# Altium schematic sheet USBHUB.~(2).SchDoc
size A
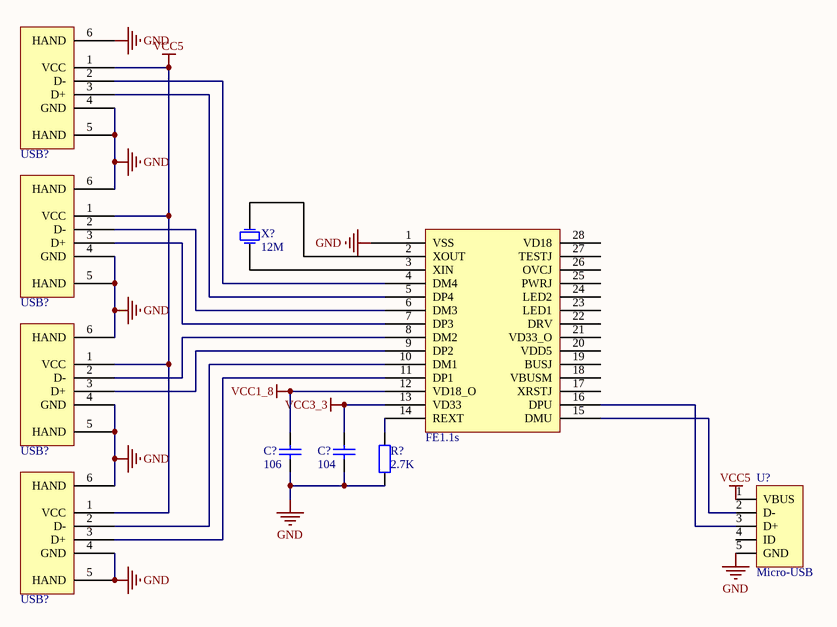
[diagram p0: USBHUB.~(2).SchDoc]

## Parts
(Parts that share a designator on the sheet are numbered #1, #2 ... from top to bottom, then left to right.)
C?#1  value 106  [2012[0805]-C]  (hidden comment: Cap1)
C?#2  value 104  [2012[0805]-C]  (hidden comment: Cap1)
FE1.1s  FE1.1s  [SSOP-28]  (value not drawn)
R?  value 2.7K  [2012[0805]-R]  (hidden comment: Res1)
U?  Micro-USB  [Micro-USB]
USB?#1  USB  [USB2.5-2V4A]  (value not drawn)
USB?#2  USB  [USB2.5-2V4A]  (value not drawn)
USB?#3  USB  [USB2.5-2V4A]  (value not drawn)
USB?#4  USB  [USB2.5-2V4A]  (value not drawn)
X?  12M  [XTAL]

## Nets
GND: C?#1.1 C?#2.1 R?.1 U?.5(GND) USB?#1.4(GND) USB?#1.5(HAND) USB?#1.6(HAND) USB?#2.4(GND) USB?#2.5(HAND) USB?#2.6(HAND) USB?#3.4(GND) USB?#3.5(HAND) USB?#3.6(HAND) USB?#4.4(GND) USB?#4.5(HAND) USB?#4.6(HAND)
VCC1_8: C?#1.2 FE1.1s.12(VD18_O)
VCC3_3: C?#2.2 FE1.1s.13(VD33)
VCC5: U?.1(VBUS) USB?#1.1(VCC) USB?#2.1(VCC) USB?#3.1(VCC) USB?#4.1(VCC)
NetFE1.1s_4: FE1.1s.4(DM4) USB?#1.2(D-)
NetFE1.1s_5: FE1.1s.5(DP4) USB?#1.3(D+)
NetFE1.1s_6: FE1.1s.6(DM3) USB?#2.2(D-)
NetFE1.1s_7: FE1.1s.7(DP3) USB?#2.3(D+)
NetFE1.1s_8: FE1.1s.8(DM2) USB?#3.2(D-)
NetFE1.1s_9: FE1.1s.9(DP2) USB?#3.3(D+)
NetFE1.1s_10: FE1.1s.10(DM1) USB?#4.2(D-)
NetFE1.1s_11: FE1.1s.11(DP1) USB?#4.3(D+)
NetFE1.1s_14: FE1.1s.14(REXT) R?.2
NetFE1.1s_15: FE1.1s.15(DMU) U?.2(D-)
NetFE1.1s_16: FE1.1s.16(DPU) U?.3(D+)

Not connected (* = marked no-connect by the designer): FE1.1s 1(VSS) 2(XOUT) 3(XIN) 17(XRSTJ) 18(VBUSM) 19(BUSJ) 20(VDD5) 21(VD33_O) 22(DRV) 23(LED1) 24(LED2) 25(PWRJ) 26(OVCJ) 27(TESTJ) 28(VD18); U? 4(ID); X? 1(OSC1) 2(OSC2)

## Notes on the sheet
- Labels drawn without touching a wire or pin: GND

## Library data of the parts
C?#1 C?#2 = Cap1: Capacitor
R? = Res1: Resistor
X? = XTAL_1: Crystal Oscillator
